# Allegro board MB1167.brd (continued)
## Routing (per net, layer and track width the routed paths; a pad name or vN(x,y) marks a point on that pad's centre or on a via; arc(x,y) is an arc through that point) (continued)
Net_246: length 0.4
  TOP w0.229: 117.36,28.08 v2(117.11,28.33)
NETB2_2: length 17.1
  TOP w0.127: B2.3 66.42,10.3 C100.2 66.42,11.94 66.04,12.32 58.67,12.32 R217.1 R216.1 55.95,10.99 B2.2
NETB3_1: length 45.4
  TOP w0.127: v1(56.9,33.96) 57.34,34.41 U22.20 ; C93.2 R212.2 73.53,13.84 v1(72.9,13.21) 71.25,13.21 68.58,10.54 68.58,8.11 B3.1
  L4_SIG w0.102: v1(72.9,13.21) 72.69,13.41 69.8,13.41 68.48,14.73 66.55,14.73 59.05,22.23 59.05,32.77 57.86,33.96 v1(56.9,33.96)
NETB3_2: length 40.4
  TOP w0.127: R211.2 C92.2 v1(69.34,13.08) 69.34,12.7 67.94,11.3 67.94,7.24 69.86,5.32 B3.2 ; U22.18 v1(57.66,33.41)
  L4_SIG w0.102: v1(57.66,33.41) 57.91,33.41 58.67,32.64 58.67,22.1 66.47,14.3 68.12,14.3 v1(69.34,13.08)
NETB3_3: length 43
  TOP w0.127: U22.19 57.53,33.9 v1(56.9,33.27) ; C91.2 R210.2 v1(67.94,13.08) 67.44,12.57 67.44,6.6 69.72,4.32 72.37,4.32 B3.3
  L4_SIG w0.102: v1(67.94,13.08) 67.13,13.89 66.37,13.89 58.42,21.84 58.42,32.38 57.91,32.89 57.28,32.89 v1(56.9,33.27)
NETB3_4: length 52.8
  TOP w0.127: v1(52.3,35.69) 52.17,35.81 51.18,35.81 50.77,35.41 U22.39 ; B3.4 79.76,11.31 v1(79.76,13.08) 79.76,13.34 R214.2 C95.2
  L4_SIG w0.102: v1(79.76,13.08) 78.49,14.35 70.26,14.35 68.99,15.62 66.55,15.62 59.74,22.43 59.74,33.1 58.19,34.65 53.14,34.65 52.3,35.48 v1(52.3,35.69)
NETB3_6: length 46.5
  TOP w0.127: C94.2 R213.2 76.71,13.59 v1(76.71,13.07) B3.6 ; U22.40 50.99,34.9 v1(51.29,35.2)
  L4_SIG w0.102: v1(76.71,13.07) 75.94,13.84 70,13.84 68.73,15.11 66.67,15.11 59.33,22.46 59.33,33 57.91,34.42 52.07,34.42 v1(51.29,35.2)
NETBT1_1: length 26.2
  TOP w0.254: BT1.1 47.88,78.23 44.07,82.04 44.07,97.79 JP9.3
NETC2_1: length 6.9
  TOP w0.508: C4.1 137.79,167.26 C2.1 R1.2 134.85,168.68 U1.6
NETC5_1: length 10
  TOP w0.508: U2.1 135.14,160.21 ; U2.1 135.14,158 ; U2.1 134.43,159.11 ; U2.1 135.85,159.11 ; C5.1 135.84,161.93 ; C5.1 135,162.89 ; C5.1 135,160.96 ; R15.2 138.91,157.61 ; R15.2 138.3,158.2 ; R15.2 137.69,157.61 ; R6.1 138.91,159.13 ; R6.1 138.3,158.53 ; R6.1 137.69,159.13
NETC6_2: length 49.3
  TOP w0.127: CN1.31 64.01,166.53 v1(64.01,163.96) 64.01,160.2 64.17,160.04 65.55,160.04 C6.2
  BOTTOM w0.127: SB34.1 39.24,145.8 38.73,146.3 38.73,154.56 44.86,160.68 52.7,160.68 55.98,163.96 v1(64.01,163.96)
NETC7_2: length 83
  TOP w0.127: C7.2 72.14,161.8 71.63,162.31 71.63,166.21 CN1.27
  TOP w0.155: v1(69.44,157.84) 69.6,157.99 69.6,159.89 69.98,160.27 C7.2
  BOTTOM w0.127: v1(69.44,157.84) 69.67,157.84 69.82,157.99 80.16,157.99 80.82,158.65 93.24,158.65 93.65,159.05 101.55,159.05 102.86,157.75 102.86,156.5 107.31,152.04 107.31,134.65 109.25,132.72 112.65,132.72 113.92,133.99 115.32,133.99 SB48.1 116.2,133.1
NETC8_2: length 28.2
  TOP w0.127: CN1.33 61.09,166.15 v1(61.09,162.62) C8.2
  BOTTOM w0.127: SB23.1 47.62,153.92 56.32,162.62 v1(61.09,162.62)
NETC9_2: length 33.6
  TOP w0.127: CN1.34 62.48,165 v1(62.48,161.99) C9.2
  BOTTOM w0.127: v1(62.48,161.99) 62.29,161.8 59.31,161.8 49.28,151.76 49.28,149.35 48.39,148.46 45.47,148.46 44.7,147.7 43.05,147.7 42.63,148.12 41.53,148.12 41.32,148.34
NETC10_2: length 78.9
  TOP w0.127: v1(67.94,155.32) 67.94,156.51 68.07,156.64 68.07,159.51 C10.2 68.83,166.47 CN1.29
  BOTTOM w0.127: v1(67.94,155.32) 67.94,155.55 69.06,156.67 69.8,156.67 70.36,157.23 80.72,157.23 81.25,157.76 95.5,157.76 96.22,158.47 100.91,158.47 101.73,157.66 101.73,157.23 106.93,152.02 106.93,134.42 109.22,132.13 SB50.1 109.22,130.56
NETC11_1: length 47.6
  TOP w0.127: v1(74.52,158.5) 74.55,158.5 74.8,158.75 R7.2 C11.1
  BOTTOM w0.127: SB53.2 50.32,132.23 50.32,137.85 55.12,142.65 55.12,147.99 61.37,154.24 64.71,154.24 68.2,157.73 68.66,157.73 69.22,158.29 74.14,158.29 74.35,158.5 v1(74.52,158.5)
NETC12_2: length 46.5
  TOP w0.127: C12.2 R8.1 78.51,159.74 v1(78.51,160.27)
  BOTTOM w0.127: v1(78.51,160.27) 77.72,160.27 77.09,159.64 73.43,159.64 73.18,159.38 68.58,159.38 68.2,159 66.55,159 63.5,155.96 61.09,155.96 53.59,148.46 53.59,143.76 SB44.2
NETC13_2: length 56.4
  TOP w0.127: C13.2 R9.1 81.97,159.59 v1(81.97,160.73)
  BOTTOM w0.127: 40.56,141.4 41.16,140.8 42.89,140.8 43.43,141.35 45.02,141.35 45.4,141.73 48.77,141.73 52.45,145.41 52.45,149.1 60.45,157.1 62.99,157.1 66.07,160.17 67.87,160.17 68.39,160.7 72.97,160.7 73.17,160.5 76.28,160.5 77.07,161.29 81.41,161.29 v1(81.97,160.73)
NETC14_2: length 52.6
  TOP w0.127: v1(85.9,162.92) 85.85,162.86 85.85,162.31 86.23,161.93 86.23,159.38 R10.1 C14.2
  BOTTOM w0.127: v1(85.9,162.92) 85.5,163.32 65.66,163.32 62.99,160.66 59.05,160.66 50.04,151.64 50.04,148.84 48.77,147.57 SB31.2
NETC15_1: length 92.6
  TOP w0.127: v1(88.9,168.91) 89.15,168.66 89.15,159.51 R11.2 R12.1 C15.1
  BOTTOM w0.127: 40.64,139.83 SB40.2 39.12,139.83 37.21,141.73 37.21,156.21 42.55,161.54 42.55,166.75 45.19,169.39 88.42,169.39 v1(88.9,168.91)
NETC16_2: length 10.6
  TOP w0.127: CN1.1 104.27,166.59 C16.2 R13.1 R14.1
NETC17_1: length 1.7
  TOP w0.127: C17.1 64.32,158.88 64.14,159.05
NETC18_2: length 78.4
  TOP w0.127: v1(69.34,156.21) 70.49,157.36 70.49,159 SB1.1 ; C18.2 70.87,158.88
  BOTTOM w0.127: SB56.1 115.32,127.76 112.67,127.76 112.27,127.36 107.87,127.36 107.59,127.64 107.59,132.87 106.22,134.24 106.22,151.51 100.89,156.84 100.41,156.84 99.2,158.05 96.22,158.05 95.66,157.48 81.51,157.48 81,156.97 70.54,156.97 69.77,156.21 v1(69.34,156.21)
NETC20_1: length 6.3
  TOP w0.203: X1.2 75.44,152.65 C20.1 R19.2
NETC21_1: length 5.7
  TOP w0.203: R17.1 C21.1 82.09,151.17 82.09,152.06 82.63,152.6 82.63,153.46 X2.1
NETC22_1: length 5.7
  TOP w0.203: X2.2 83.06,153.28 83.06,152.4 82.51,151.85 82.51,151.02 C22.1 R18.1
NETC24_2: length 2.8
  TOP w0.127: R29.1 C24.2 R30.1
NETC25_1: length 2.4
  TOP w0.127: U5.1 26.89,133.77 C25.1
NETC25_2: length 2.1
  TOP w0.127: C25.2 26.02,133.12 U5.2
NETC27_2: length 2.4
  TOP w0.127: U5.3 26.67,132.47 C27.2
NETC30_1: length 13.9
  TOP w0.254: C30.1 137.54,125.22 X4.1 145.29,125.22 JP6.1
NETC31_2: length 7.2
  TOP w0.254: X4.2 140.72,121.28 139.19,122.81 R73.2 C31.2
NETC32_1: length 12.8
  TOP w0.127: v5(81.21,134.49) U4.E11
  TOP w0.508: C32.1 80.82,127.05 80.7,127.18 79.58,128.29 v1(79.58,128.29)
  BOTTOM w0.127: v5(81.21,134.49) 80.83,134.11 80.16,134.11 80.01,133.96 80.01,132.59 79.88,132.46
  BOTTOM w0.381: v1(79.58,128.29) 79.76,128.47 79.76,130.77 79.78,130.79 79.78,132.36 79.88,132.46
NETC34_1: length 21.4
  TOP w0.508: 4.47,118.11 C35.1 ; C35.1 5.69,118.11 ; C35.1 5.08,117.46 ; CN8.6 5.46,110.88 ; CN8.6 3.46,110.88 ; CN8.6 4.46,110.14 ; CN8.7 4.46,116.17 ; CN8.7 5.46,115.43 ; CN8.7 3.46,115.43 ; C44.1 5.08,108.6 ; C44.1 4.47,107.95 ; C44.1 5.69,107.95 ; 2.44,109.01 CN8.9 1.28,108.1 ; 6.6,117.46 L1.2 ; L1.2 7.21,118.11 ; L1.2 5.99,118.11 ; L1.2 6.6,118.76 ; 2.95,118.11 C34.1 ; C34.1 4.17,118.11 ; C34.1 3.56,117.46 ; 2.95,107.95 C43.1 ; C43.1 4.17,107.95 ; C43.1 3.56,108.6 ; 1.28,118.21 CN8.8 2.44,117.31 ; 5.01,114.46 CN8.5 3.26,114.46
NETC36_1: length 8.8
  TOP w0.508: U7.1 17.09,116.26 C36.1 15.62,116.46 SB13.2 13.84,116.46 12.07,116.46 11.43,115.82 SB12.1
NETC38_1: length 8
  TOP w0.203: X5.1 27.81,113.54 C38.1 R87.2 28.7,109.86 U8.28
NETC39_1: length 7.6
  TOP w0.203: X5.2 29.34,113.54 C39.1 R87.1 29.2,110.61 U8.27
NETC40_1: length 12.4
  TOP w0.102: U9.B5 81.31,102.77 83.11,102.77 83.79,103.45 83.79,105.87 84,106.07 84,107.95
  TOP w0.127: 84,107.95 84,110.41 C40.1 R85.2
NETC41_1: length 5
  TOP w0.127: U8.29 28.2,109.72 27.81,110.11 v1(27.05,110.11) 26.92,110.11 C41.1
  BOTTOM w0.127: C142.1 26.67,110.11 v1(27.05,110.11)
NETC42_1: length 19.4
  TOP w0.254: v1(30.1,111.53) 30.23,111.53 30.86,110.9 C42.1 29.7,109.58 U8.26 ; U8.15 29.7,102.74
  TOP w0.381: v1(32,102.79) 32,101.47 C47.1 31.11,101.35 29.97,102.49 29.95,102.49 29.7,102.74
  BOTTOM w0.381: v1(32,102.79) 32,103 32.38,103.38 32.38,110.03 30.89,111.53 v1(30.1,111.53)
NETC49_2: length 1.9
  TOP w0.508: C49.2 21.15,72.45 U16.4
NETC50_2: length 19.9
  TOP w0.508: U16.1 25.27,70.48 C52.2 C50.2 ; C50.2 27.12,72.45 U16.3 ; C50.2 27.18,73.28 27.69,73.79 28.57,73.79 29.06,74.28 D12.2 D11.2 D10.2 D9.2 D8.2 D7.2
NETC60_1: length 27.3
  TOP w0.508: 21.97,46.46 Z1.2 ; Z1.2 23.17,47.5 ; Z1.2 20.76,47.5 ; Z1.2 21.97,48.54 ; C60.1 21.48,44.96 ; C60.1 20.83,45.57 ; C60.1 20.83,44.35 ; 20.7,42.38 D13.3 ; D13.3 21.37,42.89 ; D13.3 20.7,43.4
  TOP w1.143: 21.08,49.78 20.19,50.67 13.46,50.67 11.43,52.7 9.02,52.7 6.52,50.2 L3.1
NETC60_2: length 27
  TOP w0.508: 19.3,44.35 C60.2 ; C60.2 18.66,44.96 ; C60.2 19.3,45.57 ; CN17.2 9.86,34.62 ; CN17.2 5.23,34.62 ; CN17.2 7.54,33.4 ; CN17.2 7.54,35.84 ; 18.17,46.46 Z1.1 ; Z1.1 16.96,47.5 ; Z1.1 18.17,48.54 ; Z1.1 19.37,47.5 ; 19.43,42.89 19.43,43.4 ; 19.43,42.89 18.76,42.89 ; 19.43,42.89 19.43,42.38 ; CN17.3 4.45,41.94 ; CN17.3 5.66,39.62 ; CN17.3 3.23,39.62 ; CN17.3 4.45,37.31 ; L3.2 10.3,50.2 ; L3.2 7.91,50.2 ; L3.2 9.1,51.4 ; L3.2 9.1,49.01
NETC62_1: length 9
  TOP w0.508: 65.07,35.05 65.91,35.05 ; 65.91,35.05 65.91,36.02 ; 65.91,35.05 65.91,34.09 ; 65.91,35.05 66.75,35.05 ; 66.14,38.86 L5.2 65.53,38.21 ; C62.1 65.28,37.69 ; C62.1 65.28,36.47 ; C62.1 65.93,37.08 ; CN20.45 65.72,33.46
NETC62_2: length 11.3
  TOP w0.508: C62.2 63.75,37.69 ; C62.2 63.11,37.08 ; C62.2 63.75,36.47 ; L4.2 64.11,38.86 ; L4.2 62.89,38.86 ; L4.2 63.5,38.21 ; 62.61,31.24 CN20.49 63.18,32.84 ; 62.28,35.05 C70.2 ; C70.2 63.12,34.09 ; C70.2 63.12,36.02 ; C70.2 63.96,35.05 ; 64.39,33.02 64.45,32.96 CN20.47
NETC63_2: length 5.2
  TOP w0.127: U23.C9 116.97,31.48 116.97,32.13 116.46,32.64 115.7,32.64 C63.2
NETC64_1: length 5.4
  TOP w0.089: U23.D7 117.61,30.34 117.61,31.49 117.6,31.5
  TOP w0.127: 117.6,31.5 117.47,31.62 117.47,32.26 C64.1
NETC64_2: length 60.5
  TOP w0.127: v1(135.2,2.49) 136.51,1.18 CN26.2 140.37,1.18 R223.2 ; R177.1 v1(111.63,28.32) ; v1(114.58,35.18) 114.68,35.28 114.68,35.31 C64.2
  L4_SIG w0.102: v1(111.63,28.32) 111.63,18.41 119.89,10.16 127.64,10.16 130.81,6.99 130.81,4.19 132.51,2.49 v1(135.2,2.49)
  BOTTOM w0.127: v1(111.63,28.32) 111.63,30.17 112.87,31.4 112.87,34.38 113.67,35.18 v1(114.58,35.18)
NETC65_1: length 3.8
  TOP w0.089: U23.D9 117.86,31.5
  TOP w0.127: 117.86,31.5 117.86,32.38 116.71,33.53 C65.1
NETC69_1: length 7.2
  TOP w0.089: 119.61,31.5 119.61,31.01 119.61,31 119.61,30.98 119.46,30.84 119.26,30.84 119.11,30.69 119.11,30.48 118.96,30.33 118.76,30.33 118.61,30.19 118.61,29.84 118.36,29.59 U23.E6
  TOP w0.127: C69.1 121.79,33.91 121.79,33.15 121.16,32.51 120.27,32.51 119.61,31.86 119.61,31.5
NETC71_1: length 6.2
  TOP w0.089: 120.4,30.73 120.25,30.58 U23.H8
  TOP w0.127: C71.1 124.38,32.18 122.99,32.18 121.54,30.73 120.4,30.73
NETC71_2: length 5.2
  TOP w0.089: U23.G8 119.51,30.58 119.76,30.83 120.04,30.83 120.4,31.19
  TOP w0.127: 120.4,31.19 121.36,31.19 122.68,32.51 123.19,32.51 C71.2
NETC72_2: length 47.7
  TOP w0.127: U23.A7 116.34,30.1 115.06,30.1 C72.2 v1(114.05,32)
  L4_SIG w0.102: v1(114.05,32) 113.54,31.5 110.07,31.5 98.77,20.19 85.98,20.19 83.69,17.91 83.69,14.35 JP17.1
NETC73_1: length 4.8
  TOP w0.089: 120.4,30.33 119.96,30.33 119.96,30.33 119.61,30.33 119.36,30.08 U23.G7
  TOP w0.127: C73.1 123.44,31.5 122.28,30.33 120.4,30.33
NETC74_2: length 5.5
  TOP w0.089: 115.82,29.84 116.61,29.84 U23.B6
  TOP w0.127: 115.82,29.84 115.18,29.84 114.55,29.21 R177.2 C74.2
NETC75_1: length 3.9
  TOP w0.089: 120.4,29.95 120.26,30.08 U23.H7
  TOP w0.127: 120.4,29.95 123.29,29.95 C75.1
NETC76_1: length 34.9
  TOP w0.089: 120.4,29.59 120.15,29.84 119.61,29.84 U23.G6
  TOP w0.127: CN26.4 131.99,5.88 v1(132.31,6.2) ; 120.4,29.59 122.18,29.59 v1(122.56,29.21) 122.94,28.83 C76.1
  L4_SIG w0.102: v1(122.56,29.21) 124.08,27.69 125.86,27.69 127.95,25.59 127.95,21.15 132.31,16.79 v1(132.31,6.2)
NETC76_2: length 1.7
  TOP w0.127: C76.2 R178.1
NETC77_1: length 28.6
  TOP w0.089: 120.4,29.21 120.23,29.21 U23.H6
  TOP w0.127: v1(124.33,28.19) C77.1 121.79,29.21 120.4,29.21 ; CN26.6 137.32,14.33 v1(135.74,14.33)
  L4_SIG w0.102: v1(135.74,14.33) 135.28,14.33 128.22,21.39 128.22,25.96 125.98,28.19 v1(124.33,28.19)
NETC77_2: length 1.7
  TOP w0.127: C77.2 R179.1
NETC78_2: length 7.7
  TOP w0.279: U22.9 55.73,27.33 C78.2
  TOP w0.508: C78.2 56.01,26.04 56.26,25.78 C82.1 56.13,24.13 L6.2
NETC79_2: length 5.1
  TOP w0.127: U22.7 54.73,27.55 C79.2 R182.1 52.98,27.29 D16.1
NETC87_1: length 4
  TOP w0.127: U23.F1 119,26.94 119,26.42 120.14,25.27 120.14,24.89 C87.1
NETC88_1: length 2.5
  TOP w0.127: C88.1 R197.1 R196.1
NETC88_2: length 13.1
  TOP w0.254: U23.A2 116.21,27.43 115.32,27.43
  TOP w0.508: 115.32,27.43 114.93,27.04 114.29,27.04 112.78,25.53 112.78,20.07 114.17,18.67 C88.2
NETC97_1: length 5.8
  TOP w0.127: R215.2 C97.1 101.22,9.91 CN28.1
NETC98_1: length 3.1
  TOP w0.127: R220.2 R219.2 106.68,9.53 C98.1
NETC98_2: length 22.2
  TOP w0.229: U23.B3 v2(116.61,28.33)
  TOP w0.508: v1(113.92,28.19) 113.03,28.19 106.68,21.84 C98.2
  L4_SIG w0.381: v2(116.61,28.33) 116.24,28.7 114.43,28.7 v1(113.92,28.19)
NETC100_1: length 1.5
  TOP w0.127: C100.1 R218.2
NETC134_2: length 3.2
  TOP w0.127: v1(33.15,133.22) 33.25,133.12 U5.27
  BOTTOM w0.127: v1(33.15,133.22) 33.78,132.59 C134.2
NETC136_1: length 4.9
  TOP w0.127: v1(31.5,131.83) 33.53,131.83 34.19,131.17 U5.24
  BOTTOM w0.127: v1(31.5,131.83) C136.1
NETC136_2: length 4.8
  TOP w0.127: U5.28 31.91,133.77 v1(31.5,133.35)
  BOTTOM w0.127: v1(31.5,133.35) C136.2
NETC137_2: length 9.2
  TOP w0.254: v1(130.3,116.33) 130.27,116.37 U6.23 ; U6.18 v1(127.77,116.33) ; U6.37 130.77,125.31 v1(130.3,124.84)
  BOTTOM w0.508: v1(127.77,116.33) 127.38,116.72 C141.2 ; C137.2 v1(130.3,124.84) 130.3,124.08 C139.1 ; C140.1 v1(130.3,116.33)
NETC138_1: length 10.4
  TOP w0.127: U4.L11 v5(75.61,134.49)
  BOTTOM w0.127: 76.83,132.41 76.83,133.88 76.61,134.11 75.99,134.11 v5(75.61,134.49)
  BOTTOM w0.381: 76.83,132.41 76.83,132.03 77.11,131.75 77.11,131.57 78.11,130.58 78.11,126.19 C138.1
NETCN1_3: length 78
  L4_SIG w0.102: v1(117.27,121.21) 117.27,123.75 121.67,128.14 125.22,128.14 129.67,132.59 129.67,135.89 v1(130.18,136.4)
  BOTTOM w0.127: CN1.3 102.33,169.29 113.79,169.29 116.2,166.88 116.2,163.7 125.35,154.56 125.35,152.35 130.35,147.35 130.35,136.58 v1(130.18,136.4) ; SB62.2 116.08,122.4 v1(117.27,121.21)
NETCN1_5: length 64.9
  TOP w0.127: CN1.5 96.9,166.4 v1(96.9,162.13)
  BOTTOM w0.127: 47.7,144.45 48.82,144.45 51.1,146.74 51.1,149.78 60.58,159.26 62.99,159.26 66.17,162.43 84.38,162.43 85.01,161.8 86.49,161.8 86.82,162.13 v1(96.9,162.13)
NETCN1_9: length 79.4
  TOP w0.127: v1(94.11,158.22) 94.11,166.59 CN1.9
  BOTTOM w0.127: SB59.1 47.5,125.73 51.08,129.31 51.08,137.62 55.85,142.39 55.85,147.65 61.65,153.45 65.05,153.45 68.55,156.95 69.62,156.95 70.15,157.48 80.52,157.48 81.08,158.04 93.93,158.04 v1(94.11,158.22)
NETCN1_11: length 56
  TOP w0.127: v1(92.96,156.97) 92.84,157.1 92.84,161.16 91.69,162.31 91.69,166.47 CN1.11
  BOTTOM w0.127: v1(92.96,156.97) 93.55,156.39 99.03,156.39 104.75,150.67 104.75,133.55 106.3,132 106.3,126.62 106.68,126.24 110.49,126.24 110.74,125.98 SB58.2
NETCN1_13: length 84.2
  BOTTOM w0.127: CN1.13 86.58,169.04 45.72,169.04 43.05,166.37 43.05,161.54 37.59,156.08 37.59,142.37 39.41,140.55 43.73,140.55 44.2,140.08 46.61,140.08 47.37,140.84 SB39.1
NETCN1_14: length 5
  TOP w0.127: CN1.14 88.39,164.69 R11.1
NETCN1_15: length 8.5
  TOP w0.127: R10.2 85.09,160.78 85.09,162.69 84.2,163.58 84.2,166.4 CN1.15
NETCN1_17: length 8.1
  TOP w0.127: R9.2 82.8,162.94 81.92,163.83 81.92,166.65 CN1.17
NETCN1_19: length 8.1
  TOP w0.127: CN1.19 78.99,166.27 78.99,163.83 79.3,163.53 79.3,160.48 R8.2
NETCN1_21: length 62.4
  TOP w0.127: v1(78.37,159.25) 78.37,159.31 78.03,159.65 78.03,162.76 76.58,164.21 76.58,166.4 CN1.21
  BOTTOM w0.127: SB46.2 108.58,136.53 108.58,137.82 108.08,138.33 108.08,154.05 106.43,155.7 106.43,157.48 103.92,159.98 93.21,159.98 92.68,159.46 81.2,159.46 80.59,160.07 79.55,160.07 78.73,159.25 v1(78.37,159.25)
NETCN1_23: length 62.2
  TOP w0.127: v1(77.6,159.26) 77.6,160.96 75.95,162.61 75.64,162.61 74.04,164.21 74.04,166.4 CN1.23
  BOTTOM w0.127: v1(77.6,159.26) 78.11,159.77 78.73,159.77 79.32,160.35 80.75,160.35 81.38,159.72 92.46,159.72 93.05,160.31 104.33,160.31 106.93,157.71 106.93,156.21 108.46,154.69 108.46,139.19 109.22,138.43
NETCN1_26: length 5.9
  TOP w0.127: CN1.26 72.74,163.86 75.31,161.29 R7.1
NETCN2_1: length 3.1
  TOP w0.127: R3.2 CN2.1
NETCN2_3: length 3.1
  TOP w0.127: CN2.3 36.16,163.96 R5.2
NETCN2_4: length 9
  TOP w0.127: R16.1 24.77,157.1 24.77,162.69 25.91,163.83 CN2.4
NETCN3_1: length 4.8
  TOP w0.127: CN3.1 R29.2 R28.1
NETCN4_15: length 179.9
  TOP w0.127: v1(53.21,36.83) 53.21,36.96 53.23,36.98 U22.33 ; v1(150.62,149.69) CN4.15
  L4_SIG w0.102: v1(53.21,36.83) 54.1,37.72 75.18,37.72 116.33,78.87 116.33,87.05 131.04,101.75 131.04,106.4 134.37,109.73 136.75,109.73 141.02,114 142.82,114 146.18,117.35 153.47,117.35 155.19,119.08 155.19,133.86 153.8,135.25 153.8,146.52 v1(150.62,149.69)
  BOTTOM w0.127: R229.2 150.62,149.86 v1(150.62,149.69)
NETCN4_17: length 176.2
  TOP w0.127: v1(53.59,39.24) 53.73,39.1 U22.32 ; v1(150.55,148.39) 150.12,148.39 149.81,148.69 CN4.17
  L4_SIG w0.102: v1(53.59,39.24) 54.74,38.1 75.06,38.1 115.95,78.99 115.95,87.07 130.68,101.8 130.68,106.55 134.11,109.98 136.53,109.98 140.91,114.36 142.68,114.36 146.05,117.73 150.5,117.73 153.03,120.27 153.03,128.4 154.81,130.18 154.81,133.6 153.42,135 153.42,146.05 151.08,148.39 v1(150.55,148.39)
  BOTTOM w0.127: R231.1 150.55,148.41 v1(150.55,148.39)
NETCN4_18: length 32.2
  TOP w0.127: CN4.18 153.44,148.69 156.08,146.05 156.08,121.41 TP7.1
NETCN4_19: length 173.6
  TOP w0.127: v1(54.36,39.24) 54.23,39.12 U22.31 ; CN4.19 149.82,147.69 150.47,147.04 v1(150.55,147.04)
  L4_SIG w0.102: v1(54.36,39.24) 55.24,38.35 74.95,38.35 115.7,79.1 115.7,87.17 130.43,101.9 130.43,106.81 133.86,110.24 136.42,110.24 140.85,114.67 142.61,114.67 146.43,118.49 150.37,118.49 152.65,120.78 152.65,128.78 154.43,130.56 154.43,133.35 153.03,134.75 153.03,145.54 151.54,147.04 v1(150.55,147.04)
  BOTTOM w0.127: v1(150.55,147.04) 149.73,146.23 R235.1
NETCN4_32: length 155
  TOP w0.127: JP23.1 113.79,51.69 R301.1 113.79,55.5 113.28,56.01 93.73,56.01 93.09,56.64 v1(89.03,56.64) ; CN4.32 151.57,141.69 151.03,141.15 v1(151.03,140.51)
  L4_SIG w0.102: v1(89.03,56.64) 90.04,56.64 111.96,78.56 111.96,88.06 116.36,92.46 117.89,92.46 125.22,99.79 125.22,100.68 126.21,101.68 127.51,101.68 128.27,102.44 128.27,104.72 126.72,106.27 126.52,106.27 125.5,107.29 125.5,110.79 128.09,113.39 132.33,113.39 135.53,116.59 138.66,116.59 139.27,117.2 142.32,117.2 148.03,122.91 149.66,122.91 150.01,123.27 150.01,127.3 153.44,130.73 153.44,133.71 152.25,134.9 152.25,139.75 151.49,140.51 v1(151.03,140.51)
NETCN4_33: length 63.1
  TOP w0.127: v1(110.11,160.53) 109.73,160.15 SB5.1 ; v1(147.98,140.87) 148.16,140.69 CN4.33
  L4_SIG w0.102: v1(147.98,140.87) 149.48,142.37 150.88,142.37 151.12,142.61 151.12,143.01 150.85,143.28 150.85,143.99 151.38,144.53 151.38,145.16 150.88,145.67 150.11,145.67 149.31,146.47 149.31,156.76 147.37,158.7 126.42,158.7 125.65,159.46 111.18,159.46 v1(110.11,160.53)
NETCN4_34: length 21.8
  TOP w0.127: CN4.34 154.33,140.69 155.57,139.45 155.57,123.44 TP8.1
NETCN4_35: length 18.1
  TOP w0.127: TP11.1 154.05,134.75 152.4,136.4 148.97,136.4 148.21,137.16 148.21,139.19 148.71,139.69 CN4.35
NETCN4_36: length 17.7
  TOP w0.127: TP10.1 154.18,124.33 155.07,125.22 155.07,138.43 153.8,139.69 CN4.36
NETCN5_3: length 40.6
  TOP w0.127: v1(43.23,154.23) 43,154.23 42.55,154.69 CN5.3
  L4_SIG w0.102: v1(78.11,149.88) 77.87,150.11 73.03,150.11 70.54,152.6 55.8,152.6 53.26,155.14 45.77,155.14 44.86,154.23 v1(43.23,154.23)
  BOTTOM w0.127: 76.93,149.88 v1(78.11,149.88)
NETCN5_5: length 3.1
  TOP w0.127: v1(39.5,153.42) CN5.5
  BOTTOM w0.127: R224.2 v1(39.5,153.42)
NETCN5_6: length 29.3
  TOP w0.127: CN5.6 47.85,153.42 v1(49,154.56)
  L4_SIG w0.102: v1(72.39,150.11) 71.88,150.11 69.77,152.22 55.55,152.22 53.21,154.56 v1(49,154.56)
  BOTTOM w0.127: 73.76,149.88 72.62,149.88 v1(72.39,150.11)
NETCN6_3: length 37.4
  TOP w0.127: v1(111.81,154.05) 111.18,154.69 CN6.3
  L4_SIG w0.102: v1(79.22,150.22) 79.98,150.22 80.34,150.57 87.68,150.57 91.31,154.2 111.66,154.2 v1(111.81,154.05)
  BOTTOM w0.127: SB26.2 80.24,150.22 v1(79.22,150.22)
NETCN6_4: length 35
  TOP w0.127: CN6.4 114.17,154.69 113.61,154.13 v1(113.49,154.13)
  L4_SIG w0.102: v1(84.02,151.61) 84.71,150.93 87.5,150.93 91.16,154.58 111.94,154.58 112.39,154.13 v1(113.49,154.13)
  BOTTOM w0.127: SB25.2 83.95,151.54 v1(84.02,151.61)
NETCN7_2: length 32.2
  TOP w0.127: CN7.2 11.91,139.29 16.64,144.02 22.73,144.02 26.16,140.59 26.16,138.3 29.84,134.62 29.84,131.44 28.92,130.52 U5.6
NETCN7_3: length 25.1
  TOP w0.127: U5.10 25.93,127.91 24.26,126.24 17.65,126.24 14.35,129.54 14.35,133.86 11.68,136.53 CN7.3
NETCN7_6: length 34.9
  TOP w0.127: U5.5 28.68,131.17 29.21,131.7 29.21,134.49 25.65,138.05 25.65,140.34 22.35,143.64 17.27,143.64 11.68,138.05 9.53,138.05 7.49,140.08 CN7.6
NETCN7_8: length 30.4
  TOP w0.127: U5.7 27,129.87 26.8,129.67 26.8,129.29 24.26,126.75 17.91,126.75 15.11,129.54 15.11,133.86 11.3,137.67 9.4,137.67 7.49,135.76 CN7.8
NETCN8_2: length 27.8
  TOP w0.155: v1(8.44,113.97) 8.2,113.97 7.8,114.37 D4.A1 7.8,114.49 7.46,114.49 5.61,112.64 5.12,112.64 4.99,112.51 CN8.2 ; v1(23.34,104.09) 23.48,104.23 25.26,104.23 25.39,104.35 25.59,104.35 25.65,104.29 U8.8
  L4_SIG w0.13: v1(23.34,104.09) 23.2,104.23 22.74,104.23 21.38,105.59 20.62,105.59 11.6,114.6 9.47,114.6 8.84,113.97 v1(8.44,113.97)
NETCN8_3: length 27.7
  TOP w0.155: U8.7 25.71,104.8 25.65,104.74 25.23,104.74 25.11,104.61 23.48,104.61 v1(23.34,104.75) ; CN8.3 4.99,113.16 5.12,113.02 5.45,113.02 7.3,114.87 7.79,114.87 D4.A2 7.8,115.04 8.2,115.44 v1(8.38,115.44)
  L4_SIG w0.13: v1(8.38,115.44) 8.97,115.44 9.42,114.99 11.76,114.99 20.78,105.97 21.54,105.97 22.9,104.61 23.2,104.61 v1(23.34,104.75)
NETCN8_4: length 29
  TOP w0.127: v1(8.66,117.09) 8.08,117.09 7.8,116.81 D3.A2 7.06,116.53 6.48,115.95 6.48,114.94 5.35,113.81 CN8.4 ; v1(23.37,105.8) U8.5
  L4_SIG w0.102: v1(23.37,105.8) 22.94,105.8 14.61,114.13 14.61,114.71 12.22,117.09 v1(8.66,117.09)
NETCN9_1: length 35.8
  TOP w0.13: U6.17 127.27,118.34 127.21,118.4 127.21,118.69 126.85,119.04 125.14,119.04 123.95,117.86 123.95,114.35 132.72,105.59 132.72,103.98 134.59,102.11 136.78,102.11 R120.2 138.05,102.11 142.39,102.11 143.06,102.79 143.3,102.79 CN9.1
NETCN9_2: length 35.7
  TOP w0.13: U6.16 126.77,118.34 126.83,118.4 126.83,118.53 126.7,118.66 125.29,118.66 124.33,117.7 124.33,117.44 124.54,117.24 124.54,116.98 124.33,116.78 124.33,116.52 124.54,116.31 124.54,116.05 124.33,115.85 124.33,115.59 124.54,115.39 124.54,115.13 124.33,114.93 124.33,114.51 133.1,105.75 133.1,104.14 134.75,102.49 136.78,102.49 R114.2 138.05,102.49 142.23,102.49 142.9,103.16 142.9,104.01 142.77,104.14 141.73,104.14 141.6,104.01 141.6,103.63
NETCN9_3: length 28
  TOP w0.13: U6.14 125.77,116.55 125.71,116.49 125.71,114.58 130.18,110.11 136.91,110.11 R89.2 138.18,110.11 142.62,110.11 143.13,109.6 143.13,105.92 CN9.3
NETCN9_6: length 28.1
  TOP w0.13: U6.13 125.27,116.55 125.33,116.49 125.33,114.42 130.02,109.73 136.91,109.73 R97.2 138.18,109.73 142.46,109.73 142.75,109.44 142.75,107.42 142.62,107.29 141.48,107.29 141.35,107.42 141.35,108.58 141.48,108.71 141.6,108.71
NETCN9_9: length 3.7
  TOP w0.127: CN9.9 155.39,97.74 R131.1
NETCN9_10: length 39.8
  TOP w0.127: U6.28 132.97,120.54 134.51,119 134.87,119 R76.1 135.89,117.98 137.79,117.98 139.01,116.76 148.79,116.76 150.01,117.98 153.8,117.98 155.19,116.59 v1(155.32,116.59)
  BOTTOM w0.127: CN9.10 153.87,111.2 155.07,112.39 155.07,116.33 v1(155.32,116.59)
NETCN9_11: length 31.9
  TOP w0.127: U6.26 132.98,119.54 133.86,118.67 133.86,117.22 R79.1 135.86,116.43 148.97,116.43 150.01,117.47 153.54,117.47 155.39,115.62 CN9.11
NETCN9_12: length 3.7
  TOP w0.127: R78.1 153.87,116 CN9.12
NETCN11_6: length 47.8
  TOP w0.102: 82.98,107.95 82.98,104.44 U9.A4
  TOP w0.127: 82.98,107.95 82.98,108.46 v4(83.13,108.61) 82.75,108.99 82.75,110.57 R92.1 ; v3(103.5,114.68) 103.68,114.86 CN11.6
  L4_SIG w0.102: v3(103.5,114.68) 103,114.17 101.88,114.17 96.89,109.18 84.42,109.18 83.85,108.61 v4(83.13,108.61)
  BOTTOM w0.127: JP5.1 96.39,118.75 100.99,114.15 102.97,114.15 v3(103.5,114.68)
NETCN12_2: length 58.2
  TOP w0.127: R86.1 123.83,111.12 v1(123.19,110.49) 123.06,110.62 CN12.2 ; v1(146.69,79.76) 146.56,79.76 R141.1 145.8,78.25 145.94,78.11 U15.1 149.24,77.1 CN15.7
  BOTTOM w0.127: v1(123.19,110.49) 123.83,110.49 127.41,106.91 131.35,106.91 133.63,104.63 133.63,101.57 135.64,99.57 139.62,99.57 148.21,90.98 148.21,81.15 146.81,79.76 v1(146.69,79.76)
NETCN12_4: length 59.4
  TOP w0.127: CN12.4 v1(123.06,109.35) 123.83,109.35 R93.1 ; CN15.9 149.61,76.2 145.03,76.2 144.64,76.6 U15.3 144.64,78.11 144.4,78.34 R140.2 v1(145.16,79.76)
  BOTTOM w0.127: v1(123.06,109.35) 126.09,106.32 131.58,106.32 133.12,104.78 133.12,101.45 135.38,99.19 139.37,99.19 147.75,90.8 147.75,82.47 145.16,79.88 v1(145.16,79.76)
NETCN12_6: length 72.4
  TOP w0.127: U15.4 144.64,74.56 R143.1 v1(146.69,73.41) 147.83,73.41 148.46,74.04 150.62,74.04 151.26,73.41 151.26,71.5 CN15.13 ; R111.2 123.83,105.41 v1(123.19,105.41) ; R99.1 123.83,108.08 v1(123.19,108.08) CN12.6
  L4_SIG w0.102: v1(123.19,108.08) 122.68,107.57 122.68,105.92 v1(123.19,105.41)
  BOTTOM w0.127: v1(123.19,108.08) 125.58,105.69 131.67,105.69 132.61,104.75 132.61,101.32 135.28,98.65 139.19,98.65 147.32,90.53 147.32,85.47 144.65,82.8 144.65,76.33 146.69,74.3 v1(146.69,73.41)
NETCN12_8: length 47.6
  TOP w0.127: CN12.8 v1(123.19,106.81) 123.83,106.81 R101.1 ; CN15.5 147.83,83.06 145.02,83.06 144.64,83.44 U12.5 144.64,85.49 R136.1 v1(145.16,86.49)
  BOTTOM w0.127: v1(123.19,106.81) 126.11,103.89 129.67,103.89 131.32,102.23 131.32,100.97 134.49,97.79 138.81,97.79 145.16,91.44 v1(145.16,86.49)
NETCN12_10: length 63.1
  TOP w0.127: CN12.10 122.17,105.54 122.68,106.05 v1(123.19,106.05) R104.1 ; CN15.15 151.76,69.47 151.76,73.66 150.88,74.55 148.21,74.55 147.7,74.04 146.18,74.04 v1(145.92,74.3) 145.92,75.29 U15.5
  BOTTOM w0.127: v1(145.92,74.3) 144.27,75.95 144.27,84.84 142.37,86.74 142.37,93.6 138.56,97.41 133.73,97.41 130.75,100.39 130.75,101.66 129.03,103.38 125.86,103.38 v1(123.19,106.05)
NETCN12_12: length 98.8
  TOP w0.127: U12.1 v1(143.63,82.16) ; CN12.12 123.01,104.27 v1(123.27,104.52) ; SB7.1 91.82,140.84 92.65,140.02 101.92,140.02 v1(103.25,138.68)
  L4_SIG w0.102: v1(107.98,114.48) 115.39,107.06 120.27,107.06 122.81,104.52 v1(123.27,104.52)
  BOTTOM w0.127: v1(143.63,82.16) 142.89,82.16 139.19,85.85 133.86,85.85 131.57,88.14 131.57,97.16 130.43,98.3 126.62,98.3 125.76,99.16 125.76,102.64 123.88,104.52 v1(123.27,104.52) ; v1(107.98,114.48) 107.98,115.16 106.06,117.08 106.06,118.47 106.05,118.48 106.05,124.33 105.03,125.35 105.03,131.04 103.25,132.82 v1(103.25,138.68)
NETCN12_14: length 64.6
  TOP w0.127: SB8.1 101.98,140.84 103.89,138.94 v1(103.89,138.68) ; CN12.14 123.04,103 v1(123.06,103.02) 123.16,103.12 R111.1 ; v1(123.06,100.58) 123.59,100.06 U10.5
  L4_SIG w0.102: v1(123.06,103.02) 122.78,103.02 119.63,106.17 115.37,106.17 v1(107.98,113.56)
  BOTTOM w0.127: v1(103.89,138.68) 103.89,132.99 105.49,131.39 105.49,125.65 106.55,124.59 106.55,117.47 108.71,115.32 108.71,114.3 v1(107.98,113.56) ; v1(123.06,103.02) 123.7,102.39 123.7,101.22 v1(123.06,100.58)
NETCN12_16: length 67.4
  TOP w0.127: v3(98.98,144.65) SB6.1 ; CN12.16 122.81,101.73 v1(123.06,101.47) 123.18,101.36 U10.4 124.63,101.36 125.25,101.98 125.86,101.98 126.49,102.62 126.49,102.92 126.7,103.12 R113.1
  L4_SIG w0.102: v1(104.32,118.85) 104.32,118.69 106.83,116.18 106.83,113.77 115.7,104.9 119.63,104.9 v1(123.06,101.47)
  BOTTOM w0.127: v1(104.32,118.85) 104.32,119.08 103.5,119.89 103.5,130.58 101.47,132.61 101.47,142.16 v3(98.98,144.65)
NETCN12_18: length 75.9
  TOP w0.127: v1(89.66,149.86) SB3.1 ; CN12.18 122.3,100.46 v1(122.94,99.82) 123.32,99.44 124.84,99.44 125.09,99.69 125.09,101.23 125.22,101.36 U10.3
  L4_SIG w0.102: v1(103.63,118.85) 103.63,118.57 105.97,116.23 105.97,113.49 115.7,103.76 119.51,103.76 122.43,100.84 122.43,100.33 v1(122.94,99.82)
  BOTTOM w0.127: v1(103.63,118.85) 103,119.48 103,130.18 100.58,132.59 100.58,142.11 96.01,146.69 94.23,146.69 91.57,149.35 90.17,149.35 v1(89.66,149.86)
NETCN12_20: length 7.7
  TOP w0.127: 127.89,100.08 127.87,100.06 U10.1 125.99,99.45 125.48,98.93 122.44,98.93 122.18,99.19 CN12.20
NETCN13_2: length 4.7
  TOP w0.155: CN13.2 4.69,99.05 4.83,99.18 6.63,99.18 v1(6.77,99.04) 6.91,99.18 7.44,99.18 D5.D1
  BOTTOM w0.155: v1(6.77,99.04) 7.37,98.45 R284.1
NETCN13_3: length 4.7
  TOP w0.155: D5.C1 7.44,99.56 6.91,99.56 v1(6.77,99.7) 6.63,99.56 4.83,99.56 4.69,99.69 CN13.3
  BOTTOM w0.155: R283.1 7.37,100.29 v1(6.77,99.7)
NETCN13_4: length 7
  TOP w0.127: D5.A3 8.5,101.48 R117.1 6.35,101.6 6.35,100.97 5.73,100.34 CN13.4
NETCN14_2: length 4.7
  TOP w0.155: CN14.2 4.69,84.69 4.83,84.83 6.63,84.83 v1(6.77,84.69) 6.91,84.83 7.44,84.83 D6.D1
  BOTTOM w0.155: R288.1 7.37,84.09 v1(6.77,84.69)
NETCN14_3: length 4.7
  TOP w0.155: CN14.3 4.69,85.34 4.83,85.21 6.63,85.21 v1(6.77,85.35) 6.91,85.21 7.44,85.21 D6.C1
  BOTTOM w0.155: v1(6.77,85.35) 7.37,85.94 R286.1
NETCN14_4: length 76.8
  TOP w0.127: CN14.4 5.09,85.99 6.35,87.25 v1(7.87,87.25) 8,87.25 8.5,86.75 D6.A3 ; v1(39.37,130.56) 38.99,130.56 38.1,129.67 38.1,126.36 36.58,124.84 34.04,124.84 v1(33.66,125.22)
  BOTTOM w0.127: v1(7.87,87.25) 23.88,87.25 35.81,99.19 35.81,118.62 34.67,119.76 34.67,124.08 33.66,125.09 v1(33.66,125.22) ; 40.64,130.56 v1(39.37,130.56)
NETCN15_3: length 40.7
  TOP w0.127: v1(146.56,86.49) R137.1 145.94,85.58 U12.4 145.94,83.69 146.19,83.44 149.99,83.44 CN15.3 ; R112.1 v1(126.95,104.65) R113.2
  BOTTOM w0.127: v1(146.56,86.49) 146.69,86.61 146.69,90.55 139.06,98.17 134.87,98.17 132.08,100.97 132.08,103 130.43,104.65 v1(126.95,104.65)
NETCN15_11: length 6.4
  TOP w0.508: CN15.11 149.1,73.03 148.08,72.01 R144.1 R145.2
NETCN15_17: length 4.2
  TOP w0.127: CN15.17 150.11,65.53 R148.2
NETCN15_19: length 4.3
  TOP w0.127: CN15.19 149.86,62.48 R149.2
NETCN16_1: length 96.7
  TOP w0.127: v1(109.37,80.44) 109.35,80.42 109.35,71.55 136.45,44.45 138.18,44.45 R162.2 140.08,43.69 140.56,44.17 CN16.1
  BOTTOM w0.127: R281.1 108.58,120.9 108.08,120.4 108.08,118.36 110.44,116 110.44,110.11 109.27,108.94 109.27,91.69 110.31,90.65 110.31,81.43 109.37,80.49 v1(109.37,80.44)
NETCN16_2: length 96.5
  TOP w0.127: CN16.2 140.39,45.27 140.34,45.21 R161.2 138.18,45.97 135.64,45.97 109.83,71.78 109.83,80.92 v1(109.35,81.41)
  BOTTOM w0.127: R275.1 107.7,120.9 107.7,118.24 110.03,115.9 110.03,110.34 108.92,109.22 108.92,91.47 109.88,90.5 109.88,81.94 v1(109.35,81.41)
NETCN16_3: length 91.5
  TOP w0.127: v1(110.39,80.44) 110.39,71.98 134.87,47.5 138.18,47.5 R160.2 139.3,46.37 CN16.3
  BOTTOM w0.127: SB63.1 109.22,117.98 110.87,116.33 110.87,109.8 109.63,108.56 109.63,91.9 110.79,90.73 110.79,80.82 110.41,80.44 v1(110.39,80.44)
NETCN16_7: length 96.6
  TOP w0.127: CN16.7 138.97,50.77 R158.2 138.18,51.56 131.72,51.56 110.9,72.39 110.9,80.77 v1(109.32,82.35)
  BOTTOM w0.127: SB61.2 110.74,123.57 110.36,123.19 108.25,123.19 107.19,122.12 107.19,117.98 109.6,115.57 109.6,110.57 108.51,109.47 108.51,91.26 109.4,90.37 109.4,82.42 v1(109.32,82.35)
NETCN16_8: length 99
  TOP w0.127: v1(112.52,80.9) 111.26,79.63 111.26,72.95 131.11,53.09 138.18,53.09 R157.2 139.39,51.87 CN16.8
  BOTTOM w0.127: R260.1 116.46,128.27 116.71,128.27 118.11,126.87 118.11,122.12 118.39,121.84 118.39,119.79 113.16,114.55 113.16,92.71 112.52,92.08 v1(112.52,80.9)
NETCN16_10: length 5.2
  TOP w0.127: R154.2 150.01,55.88 CN16.10
NETCN17_1: length 10.7
  TOP w0.508: D13.1 20.07,39.91 ; D13.1 21.37,39.4 ; D13.1 20.07,38.89 ; D13.1 18.76,39.4 ; CN17.1 11.86,39.62 ; CN17.1 10.64,37.31 ; CN17.1 9.43,39.62 ; CN17.1 10.64,41.94
NETCN19_4: length 2.3
  TOP w0.127: R165.2 CN19.4
NETCN20_22: length 2.8
  TOP w0.127: CN20.22 80.96,24.45 R192.1
NETCN20_39: length 20.1
  TOP w0.127: U22.27 56.23,37.37 v1(56.74,36.86) ; v1(70.23,35.64) 70.18,35.64 69.53,34.99 CN20.39
  L4_SIG w0.102: v1(70.23,35.64) 69.93,35.94 58.37,35.94 57.45,36.86 v1(56.74,36.86)
NETCN20_43: length 116.6
  TOP w0.127: CN20.43 66.99,33.21 73.96,40.18 v1(75.34,40.18)
  BOTTOM w0.127: SB60.1 116.99,123.04 116.99,122.28 117.75,121.51 117.75,120.45 111.86,114.55 111.86,109.52 110.36,108.03 110.36,92.48 112.01,90.83 112.01,80.64 87.88,56.52 87.88,55.3 75.34,42.75 v1(75.34,40.18)
NETCN21_2: length 19
  TOP w0.155: CN21.2 11.49,23.89 11.49,23.73 11.73,23.5 13.97,23.5 14.35,23.88 14.35,28.19 12.07,30.48 12.07,34.29 12.76,34.99 14.16,34.99 14.18,35.01 14.19,35.01 14.73,35.55 R166.1
NETCN21_3: length 21.2
  TOP w0.155: CN21.3 11.11,23.89 11.11,23.58 11.57,23.11 14.13,23.11 14.73,23.72 14.73,28.35 12.45,30.64 12.45,34.13 12.92,34.61 14.16,34.61 14.18,34.59 14.19,34.59 14.73,34.05 R169.1 R171.1
NETCN22_2: length 98
  TOP w0.127: U20.6 135.89,37.47 136.14,37.21 v1(136.14,36.96) 136.14,35.94 134.87,34.67 134.87,30.99 135.84,30.02 138.63,30.02 142.24,26.42 142.24,20.83 140.84,19.43 140.84,17.93 D14.1 145.12,16.7 CN22.2
  BOTTOM w0.127: v1(136.14,36.96) 137.97,38.79 137.97,59.92 127.56,70.33 127.56,95.05 JP12.2
NETCN22_5: length 10
  TOP w0.127: R174.2 145.8,24.64 CN22.5
NETCN22_7: length 35.3
  TOP w0.127: CN22.7 143.27,17.4 D14.2 142.07,19.64 142.88,20.45 142.88,26.67 138.94,30.61 136.14,30.61 135.51,31.24 135.51,34.42 137.41,36.32 R164.1 136.78,38.73 U20.7
NETCN22_9: length 14.8
  TOP w0.127: R170.2 144.04,27.91 145.21,27.91 148.59,24.54 CN22.9
NETCN24_5: length 5.3
  TOP w0.127: CN24.5 123.72,18.81 122.3,17.4 121.54,17.4 R198.1
NETCN25_2: length 8.1
  TOP w0.127: R222.1 117.47,2.54 116.12,1.18 CN25.2
NETCN25_3: length 4.2
  TOP w0.127: CN25.3 115.95,4.53 R221.1
NETCN25_4: length 2.5
  TOP w0.127: R220.1 107.57,5.94 CN25.4
NETCN25_6: length 3.1
  TOP w0.127: CN25.6 115.51,15.47 115.82,15.79 R196.2
NETD1_1: length 106
  TOP w0.127: U5.20 30.95,128.56 v1(30.35,129.16) ; D1.1 v1(97.03,155.52)
  L4_SIG w0.102: v1(97.03,155.52) 95.68,155.52 92.46,158.75 80.9,158.75 80.52,158.37 75.69,158.37 74.55,159.51 35.94,159.51 32.26,155.83 32.26,146.3 27.69,141.73 27.69,131.83 v1(30.35,129.16)
NETD1_2: length 3
  TOP w0.127: JP1.1 98.44,150.13 D1.2
NETD2_2: length 2.4
  TOP w0.127: D2.2 32.51,139.02 JP3.1
NETD5_C3: length 135.5
  TOP w0.155: D5.C3 8.56,99.56 9.09,99.56 v1(9.23,99.7)
  L4_SIG w0.13: v1(113.26,130.02) 112.99,130.29 112.99,130.46 113.14,130.61 114.22,130.61 114.81,130.02 114.81,123.25 113.28,121.72 110.31,121.72 109.07,120.47 99.24,120.47 96.9,118.14 59.21,118.14 57.51,119.84 50.47,119.84 47.88,117.25 47.88,115.14 38.05,105.31 38.05,103.17 33.27,98.4 25.78,98.4 24.18,100 10.26,100 9.82,99.56 9.37,99.56 v1(9.23,99.7)
  BOTTOM w0.127: v1(9.23,99.7) 8.89,100.04 R283.2 ; SB52.1 115.75,129.72 115.49,129.72 115.06,129.29 114.02,129.29 113.28,130.02 v1(113.26,130.02)
NETD15_2: length 1.9
  TOP w0.127: D15.2 41.29,13.97 R209.1
NETJP3_2: length 13.6
  TOP w0.127: U5.16 v1(33.66,125.96)
  BOTTOM w0.127: v1(33.66,125.96) 33.66,126.75 29.97,130.43 JP3.2
NETJP5_3: length 129.9
  TOP w0.127: JP5.3 103.38,124.46 v1(104.27,123.57) ; v1(86.36,55.37) 88.16,53.57 90.2,53.57 95.5,48.26 95.5,23.11 91.31,18.92 87.76,18.92 JP18.3
  BOTTOM w0.127: v1(86.36,55.37) 86.36,56.64 106.81,77.09 106.81,115.32 104.78,117.35 104.78,123.06 v1(104.27,123.57)
NETJP6_2: length 20
  TOP w0.127: v1(134.09,123.7) 133.93,123.54 U6.34
  L4_SIG w0.102: JP6.2 146.18,124.21 142.24,128.14 140.16,128.14 138.35,126.34 136.73,126.34 v1(134.09,123.7)
NETJP6_3: length 53.9
  L4_SIG w0.102: v1(117.25,125.48) 117.25,126.57 134.11,143.43 139.24,143.43 143.59,139.09 143.59,128.57 145.41,126.75 JP6.3
  BOTTOM w0.127: SB57.1 v1(117.25,125.48)
NETJP7_1: length 14.3
  TOP w0.127: U5.17 31.11,126.61 28.64,124.14 23.43,124.14 JP7.1
NETJP7_2: length 138.6
  TOP w0.127: v1(36.83,121.79) 20.83,121.79 19.68,122.94
  BOTTOM w0.127: v1(36.83,121.79) 37.08,121.54 37.08,113.41 42.65,107.85 42.65,88.7 52.81,78.54 52.81,69.11 58.22,63.7 58.22,44.63 54.31,40.72 52.27,40.72 49.53,37.97 49.53,30.25 55.75,24.03 55.75,21.08 57.66,19.18 JP14.1
NETJP7_3: length 161.2
  TOP w0.127: v1(136.53,171.32) 136.75,171.1 U1.4
  BOTTOM w0.127: 17.14,122.94 14.1,125.98 14.1,144.53 17.14,147.57 21.59,147.57 31.11,157.1 32.38,157.1 35.94,160.66 35.94,166.24 41.15,171.45 136.4,171.45 v1(136.53,171.32)
NETJP8_2: length 77
  TOP w0.127: JP8.2 111.76,101.35 115.57,97.54 117.02,97.54 v1(123.37,91.19) ; v1(127.89,36.32) 128.02,36.2 U20.4
  BOTTOM w0.127: v1(123.37,91.19) 123.32,91.19 122.17,90.04 122.17,68.1 127.36,62.92 127.36,36.86 v1(127.89,36.32)
NETJP9_2: length 111.5
  TOP w0.254: 41.15,103.25 39.5,104.9 39.5,115.95 v1(35.69,119.76) ; U4.C1 82.93,143.41 v1(82.93,147.07)
  L4_SIG w0.254: v1(36.32,153.67) 41.27,158.62 53.34,158.62 58.8,153.16 v3(68.45,153.16)
  BOTTOM w0.254: v1(36.32,153.67) 36.32,143.13 35.86,142.67 35.86,137.44 35.18,136.75 35.18,120.27 v1(35.69,119.76) ; v3(68.45,153.16) 68.45,152.65 73,148.11 73,148.09 73.16,147.93 73.18,147.93 74.04,147.07 v1(82.93,147.07)
NETJP10_2: length 11
  TOP w0.102: U9.B4 81.43,103.89 81.99,103.89 82.59,104.48 v5(82.59,104.65)
  TOP w0.127: JP10.2 87.76,101.22 R116.1 86.79,102.74 86.31,103.23 v1(86.31,103.68)
  L4_SIG w0.102: v1(86.31,103.68) 83.55,103.68 v5(82.59,104.65)
NETJP11_2: length 72.9
  TOP w0.127: JP11.2 113.51,96.77 121.06,89.23 122.94,89.23 v1(123.32,89.61) ; U20.8 137.29,40.01 R163.1 v1(137.41,41.02)
  BOTTOM w0.127: v1(123.32,89.61) 123.32,69.34 134.65,58.01 134.65,43.79 v1(137.41,41.02)
NETJP11_3: length 76.7
  TOP w0.127: v1(122.68,89.71) 121.36,89.71 JP11.3 ; R168.1 v1(136.55,34.54)
  BOTTOM w0.127: v1(136.55,34.54) 134.16,36.93 134.16,57.86 122.68,69.34 v1(122.68,89.71)
NETJP12_1: length 60.9
  TOP w0.127: R164.2 v1(138.94,38.99)
  BOTTOM w0.127: v1(138.94,38.99) 138.38,39.55 138.38,60.53 128.37,70.54 128.37,93.32 JP12.1
NETJP15_2: length 39.2
  TOP w0.127: R209.2 R208.1 38.42,15.56 38.42,17.08 37.85,17.65 JP15.2 ; v1(32.59,33.71) 32.59,34.87 32.06,35.41 U21.39
  L4_SIG w0.102: JP15.2 41.4,17.65 43.69,19.94 43.69,26.01 38.89,30.81 35.48,30.81 v1(32.59,33.71)
NETJP16_2: length 25.4
  TOP w0.127: JP16.2 46.61,17.14 46.61,27.43 44.32,29.72 44.32,31.93 42.61,33.64 42.61,34.1 41.8,34.9 v1(41.17,34.9) U21.21
  BOTTOM w0.127: R289.2 40.03,34.9 v1(41.17,34.9)
NETJP18_1: length 40.4
  TOP w0.127: U23.A9 v1(115.73,31.08)
  L4_SIG w0.102: JP18.1 88.9,14.99 88.9,18.41 89.79,19.3 98.42,19.3 110.23,31.11 114.2,31.11 114.51,31.42 115.39,31.42 v1(115.73,31.08)
NETJP19_1: length 42.4
  TOP w0.089: U23.C6 117.36,29.58 117.11,29.83 117.11,30.21 116.98,30.34 115.84,30.34 115.82,30.35
  TOP w0.127: v1(114.94,30.99) 115.57,30.35 115.82,30.35
  L4_SIG w0.102: JP19.1 93.09,14.61 108.08,14.61 109.22,15.75 109.22,27.94 110.79,29.51 113.46,29.51 v1(114.94,30.99)
NETJP19_3: length 123.8
  TOP w0.127: v1(87.12,55.75) 88.67,54.2 90.32,54.2 96.27,48.26 96.27,22.86 JP19.3
  BOTTOM w0.127: R280.2 116.08,119.38 111.25,114.55 111.25,109.65 109.93,108.33 109.93,92.18 111.23,90.88 111.23,80.62 87.12,56.52 v1(87.12,55.75)
NETJP20_1: length 306.3
  TOP w0.127: U5.13 26.52,125.96 v1(26.42,125.86) ; U1.3 v1(137.7,171.32)
  L4_SIG w0.102: v1(30.61,96.77) 30.61,94.49 29.34,93.22 29.34,65.41 33.5,61.24 33.5,36.73 35.41,34.82 38.02,34.82 41.53,31.32 44.63,31.32 v1(44.96,30.99)
  BOTTOM w0.127: v1(30.61,96.77) 30.61,96.9 33.91,100.2 33.91,110.87 34.8,111.76 34.8,116.08 31.11,119.76 31.11,124.84 30.1,125.86 v1(26.42,125.86) 17.4,125.86 14.48,128.78 14.48,144.27 17.27,147.07 21.59,147.07 31.11,156.59 32.64,156.59 36.45,160.4 36.45,166.12 41.4,171.07 135.64,171.07 135.89,170.81 137.16,170.81 137.67,171.32 v1(137.7,171.32) ; v1(44.96,30.99) 45.19,30.76 48.34,30.76 52.6,26.49 52.6,24.49 54.79,22.3 54.79,20.29 56.59,18.49 56.59,15.04 JP20.1
NETJP20_2: length 340.8
  L4_SIG w0.102: v1(29.97,96.01) 29.97,94.49 29.08,93.6 29.08,65.33 33.22,61.19 33.22,36.6 35.31,34.52 37.95,34.52 41.61,30.86 v1(43.69,30.86) ; v1(137.7,168.68) 137.7,164.11 134.8,161.21 127.64,161.21 126.67,162.18 121.64,162.18 119.99,163.83 109.09,163.83 105.79,160.53 103,160.53 100.46,157.99 v1(100.2,157.99) 98.93,157.99 97.54,159.38 96.27,159.38 93.47,162.18 84.07,162.18 83.06,163.19 56.39,163.19 55.5,162.31 39.62,162.31 v1(38.48,161.16)
  BOTTOM w0.127: JP20.2 56.21,15.06 56.21,18.26 54.25,20.22 54.25,22.12 52.2,24.18 52.2,26.32 48.17,30.35 44.2,30.35 v1(43.69,30.86) ; SB54.1 107.95,130.56 107.95,132.99 106.58,134.37 106.58,151.71 100.3,157.99 v1(100.2,157.99) ; v1(29.97,96.01) 31.5,96.01 34.29,98.81 34.29,110.67 35.05,111.43 35.05,116.33 31.5,119.89 31.5,125.22 30.38,126.34 17.55,126.34 14.99,128.91 14.99,144.4 17.02,146.43 21.59,146.43 31.27,156.11 32.67,156.11 37.08,160.53 37.85,160.53 v1(38.48,161.16)
NETJP21_1: length 43.2
  TOP w0.127: U23.G1 119.36,26.56 120.78,25.15 v1(120.78,24.89)
  L4_SIG w0.089: 119.94,28.13 119.94,26.92 120.19,26.67
  L4_SIG w0.102: v1(120.78,24.89) 120.78,26.09 120.19,26.67 ; 119.94,28.13 118.98,29.08 118.87,29.08 117.6,30.35 117.6,30.99 117.25,31.34 117.25,31.65 114.05,34.85 114.05,36.07 114.44,36.46 114.44,37.33 113.92,37.85 113.92,46.35 116.84,49.28 v1(116.84,57.91)
  BOTTOM w0.127: JP21.1 v1(116.84,57.91)
NETJP21_2: length 151.8
  TOP w0.127: v1(53.26,79.86) 53.85,79.27 53.85,77.83 67.6,64.08 67.6,60.06 68.9,58.76 95.84,58.76 97.28,60.2 109.09,60.2 111.38,57.91
  L4_SIG w0.102: v1(36.58,126.87) 35.31,128.14 35.31,143.26 38.23,146.18 38.23,147.7 v1(39.24,148.72)
  BOTTOM w0.127: SB24.1 39.24,149.22 v1(39.24,148.72) ; v1(53.26,79.86) 53.24,79.86 44.04,89.05 44.04,108.61 37.85,114.81 37.85,125.48 36.58,126.75 v1(36.58,126.87)
NETJP21_3: length 135
  TOP w0.127: SB11.2 77.98,121.41 79.5,119.89 106.68,119.89 109.98,116.59 120.02,116.59 124.08,112.52 v1(124.46,112.52) ; R75.1 135,120.02 133.86,121.16 133.6,121.16 v1(133.48,121.28) 133.22,121.54 U6.30
  BOTTOM w0.127: JP21.3 109.98,59.05 109.98,62.87 111.12,64.01 113.18,64.01 121.54,72.36 121.54,92.66 125.07,96.19 125.07,102.57 123.7,103.94 122.89,103.94 122.43,104.39 122.43,110.74 123.19,111.51 123.95,111.51 124.46,112.01 v1(124.46,112.52) 125.98,112.52 126.87,113.41 130.94,113.41 132.59,115.06 132.59,120.4 v1(133.48,121.28)
NETJP22_1: length 43.3
  TOP w0.089: U23.F2 119.11,27.83 120.07,27.83 120.37,27.53 v2(120.4,27.53)
  L4_SIG w0.102: v1(116.84,61.85) 117.35,61.34 117.35,48.77 114.48,45.9 114.48,38.05 115.19,37.34 115.19,34.39 118.34,31.24 118.52,31.24 120.4,29.36 v2(120.4,27.53)
  BOTTOM w0.127: JP22.1 116.08,62.61 v1(116.84,61.85)
NETJP22_2: length 152.7
  TOP w0.127: v1(57.15,144.91) 52.7,144.91 51.05,146.56 v1(48.77,146.56) ; v1(47.12,115.44) 47.12,89.28 55.5,80.9 55.5,77.34 68.2,64.64 68.2,60.45 69.24,59.41 94.54,59.41 96.34,61.21 109.98,61.21 111.38,62.61
  BOTTOM w0.127: v1(47.12,115.44) 47.12,120.65 50.04,123.57 50.04,125.22 54.48,129.67 54.48,138.68 57.15,141.35 v1(57.15,144.91) ; SB22.2 48.26,146.05 v1(48.77,146.56)
NETJP22_3: length 132.5
  TOP w0.127: SB10.2 77.98,124.97 76.96,123.95 76.96,120.9 78.61,119.25 100.46,119.25 100.58,119.38 106.17,119.38 109.86,115.7 119.76,115.7 v1(123.19,112.27) ; U6.31 133.48,122.04 v1(133.6,121.92)
  BOTTOM w0.127: JP22.3 110.87,64.64 112.57,64.64 120.9,72.97 120.9,93.04 124.61,96.75 124.61,102.34 123.39,103.56 122.58,103.56 121.92,104.22 121.92,111 v1(123.19,112.27) 125.22,114.3 130.05,114.3 131.83,116.08 131.83,120.9 132.84,121.92 v1(133.6,121.92)
NETJP23_3: length 3.4
  TOP w0.127: R300.1 109.98,52.7 JP23.3
NETJP24_1: length 63.7
  TOP w0.127: JP24.1 40.89,95.5 R302.1 37.97,96.14 37.97,104.14 38.73,104.9 38.73,114.81 v1(34.54,119) ; R30.2 22.23,147.45 22.86,146.81 v1(22.99,146.81)
  BOTTOM w0.127: v1(34.54,119) 33.66,119 33.02,119.63 33.02,125.73 28.07,130.68 28.07,141.1 22.99,146.18 v1(22.99,146.81)
NETJP24_3: length 2.6
  TOP w0.127: JP24.3 40.77,91.06 R299.1
NETL2_1: length 19.5
  TOP w0.508: v1(17.65,106.17) 19.56,106.17 19.94,106.55 R103.2 ; L2.1 R84.2 v1(11.43,113.06) SB12.2
  L4_SIG w0.508: v1(11.43,113.06) 11.43,111.38 16.64,106.17 v1(17.65,106.17)
NETLD1_2: length 110.5
  TOP w0.127: LD1.2 R207.2 27.3,13.97 27.94,14.61 v1(27.94,16.13) ; R299.2 v1(39.88,89.53)
  BOTTOM w0.127: v1(39.88,89.53) 40.92,89.53 52.07,78.38 52.07,68.83 57.66,63.25 57.66,45.21 53.77,41.33 51.49,41.33 49.02,38.86 49.02,36.32 45.09,32.38 44.2,32.38 42.8,30.99 42.8,27.94 43.56,27.18 43.56,19.3 41.66,17.4 36.83,17.4 35.56,16.13 v1(27.94,16.13)
NETLD2_2: length 2.5
  TOP w0.127: LD2.2 R206.2
NETLD3_2: length 128.7
  TOP w0.127: R205.2 v1(22.35,13.08) LD3.2 ; v1(99.44,19.3) 99.44,49.4 104.52,54.48 R300.2
  BOTTOM w0.127: v1(99.44,19.3) 67.59,19.3 64.64,16.35 64.64,13.43 59.97,8.76 57.5,8.76 56.87,9.4 30.23,9.4 26.54,13.08 v1(22.35,13.08)
NETLD4_2: length 2.5
  TOP w0.127: R204.2 LD4.2
NETLD5_1: length 1.5
  TOP w0.127: LD5.1 R96.1
NETLD5_2: length 2.4
  TOP w0.254: LD5.2 v1(10.16,110.74)
  BOTTOM w0.254: T6.3 v1(10.16,110.74)
NETLD6_1: length 2.2
  TOP w0.508: LD6.1 v1(16,107.82)
  BOTTOM w0.508: v1(16,107.82) R282.1
NETLD6_2: length 21.9
  TOP w0.254: R122.2 24.14,101.09 25.67,102.62 26.69,102.62 27.2,103.12 U8.10
  TOP w0.508: R122.2 R121.2 v1(22.86,102.49) ; v1(14.99,109.6) 15.75,110.36 LD6.2 17.09,111.45 U7.3
  L4_SIG w0.508: v1(14.99,109.6) 15.37,109.6 22.48,102.49 v1(22.86,102.49)
NETLD7_1: length 1.5
  TOP w0.127: R118.1 LD7.1
NETLD7_2: length 2.7
  TOP w0.254: LD7.2 13.72,101.85 v1(13.97,101.85)
  BOTTOM w0.254: T7.3 13.84,102.02 13.97,101.9 v1(13.97,101.85)
NETLD8_1: length 1.5
  TOP w0.127: R133.1 LD8.1
NETLD8_2: length 6.2
  TOP w0.508: LD8.2 8.89,92.05 ; LD8.2 8.89,90.83 ; LD8.2 9.54,91.44 ; 11.62,92.51 U11.3 12.14,93.29 ; 11.43,90.4 R134.2 10.83,89.79 ; 11.43,90.83 R132.2 ; R132.2 10.83,91.44 ; R132.2 11.43,92.05
NETLD9_1: length 1.5
  TOP w0.127: LD9.1 R135.1
NETLD9_2: length 2.9
  TOP w0.127: LD9.2 13.8,85.51 T2.3
NETLD10_1: length 1.5
  TOP w0.127: LD10.1 R142.1
NETLD11_1: length 1.7
  TOP w0.127: R200.2 LD11.1
NETLD11_2: length 56
  TOP w0.127: LD11.2 v1(13.34,16.51)
  TOP w0.508: U17.8 32.72,55.84 v1(32.64,55.75) 31.88,54.99 R156.2
  BOTTOM w0.127: v1(13.34,16.51) 13.84,17.02 21.69,17.02 25.91,21.23 25.91,24.49 29.21,27.79 29.21,32.56 30.78,34.14 30.78,53.9 v1(32.64,55.75)
NETLD12_2: length 1.9
  TOP w0.127: LD12.2 15,13.7 R201.2
NETLD12_3: length 1.9
  TOP w0.127: R202.2 16.5,13.73 LD12.3
NETLD12_4: length 5.3
  TOP w0.127: R203.1 17.78,10.45 LD12.4
NETR2_2: length 2.6
  TOP w0.508: U1.1 139.6,168.51 R2.2
NETR4_2: length 2.7
  TOP w0.127: R4.2 SW1.2
NETR20_1: length 13.8
  TOP w0.127: R21.1 R20.1 84.58,147.57 84.58,144.82 v3(84.61,144.82) ; v5(81.21,140.09) U4.E5
  L4_SIG w0.102: v5(81.21,140.09) 81.57,140.44 82.07,140.44 82.37,140.74 82.37,140.95 82.66,141.24 82.87,141.24 83.59,141.96 83.59,143.15 84.58,144.15 84.58,144.81 84.6,144.82 v3(84.61,144.82)
NETR22_1: length 14.2
  TOP w0.102: 76.81,144.02 U4.K1
  TOP w0.127: R22.1 71.88,148.84 73.66,147.07 76.07,147.07 76.81,146.33 76.81,144.02
NETR24_1: length 13.1
  TOP w0.127: R24.1 71.5,147.83 74.93,144.4 76.07,144.4 76.45,144.02 76.45,143.05 76.44,143.04 76.44,142.73 76.45,142.72 76.45,142.37 76.73,142.09 U4.K2
NETR25_1: length 3.1
  TOP w0.203: R25.1 137.47,146.56 X3.1
NETR26_1: length 12.6
  TOP w0.127: U4.L2 75.61,142.49 75.61,143.26 75.21,143.66 74.4,143.66 73.79,144.27 73.28,144.27 72.9,144.65 72.9,145.8 71.25,147.45 68.83,147.45 68.2,146.81 R26.1
NETR27_1: length 2.2
  TOP w0.127: R28.2 R27.1
NETR27_2: length 172.5
  TOP w0.127: v1(22.23,144.53) 16.64,144.53 R27.2
  L4_SIG w0.102: v1(26.49,92.43) 27,91.92 27,86.66 27.18,86.49 27.18,64.72 30.48,61.42 30.48,36.45 35.86,31.06 39.01,31.06 44.07,26.01 44.07,19.81 41.53,17.27 41.53,9.4 37.72,5.59 RV1.2
  BOTTOM w0.127: v1(26.49,92.43) 28.55,92.43 35.43,99.31 35.43,116.33 31.88,119.89 31.88,125.48 27.51,129.84 27.51,140.39 23.37,144.53 v1(22.23,144.53)
NETR31_1: length 11
  TOP w0.127: U4.B1 83.21,143.18 83.92,143.89 86.74,143.89 88.77,145.92 R31.1 89.79,146.56 89.66,146.69 SB3.2 SB4.2
NETR34_1: length 81.2
  TOP w0.127: v1(98.93,145.92) 98.17,146.69 93.16,146.69 92.65,146.17 92.65,145.99 91.95,145.29 90.42,145.29 R34.1 88.39,144.65 87.12,143.38 83.95,143.38 83.58,143.01 83.58,142.73 83.21,142.37 U4.B2 ; v1(127.03,102.67) 127.03,102.59 SB17.2 SB18.2 SB16.2
  L4_SIG w0.102: v1(127.03,102.67) 127,102.69 125.97,102.69 123.69,104.98 122.99,104.98 120.14,107.82 116.08,107.82 v1(105.61,118.29)
  BOTTOM w0.127: v1(98.93,145.92) 102.36,142.49 102.36,132.82 104.52,130.66 104.52,125.09 105.28,124.33 105.28,118.62 v1(105.61,118.29)
NETR35_1: length 10.2
  TOP w0.127: SB6.2 92.71,143.89 90.3,143.89 R35.1 88.01,143.38 87.51,142.89 U4.A1
NETR37_1: length 10.4
  TOP w0.127: SB8.2 92.65,141.67 90.36,141.67 R37.1 89.25,141.7 84.82,141.7 84.43,142.09 U4.A2
NETR39_1: length 31.5
  TOP w0.127: v1(99.19,138.18) 93.44,138.18 92.49,139.13 90.36,139.13 R39.1 89.79,140.59 SB7.2 87.41,140.84 86.93,141.32 84.04,141.32 U4.A3
  L4_SIG w0.102: v1(111.82,137.97) 108.53,137.97 108.2,138.3 105.03,138.3 104.52,137.79 99.57,137.79 v1(99.19,138.18)
  BOTTOM w0.127: R247.2 111.12,137.29 111.81,137.97 v1(111.82,137.97)
NETR41_1: length 10.2
  TOP w0.127: U4.L3 v5(75.61,141.69) ; v1(68.2,139.7) 67.56,139.06 R41.1
  L4_SIG w0.102: v5(75.61,141.69) 75.61,141.65 75.23,141.27 71.15,141.27 69.57,139.7 v1(68.2,139.7)
NETR42_1: length 9.7
  TOP w0.127: v5(74.81,140.09) U4.M5 ; v1(68.2,137.29) 68.07,137.16 R42.1
  L4_SIG w0.102: v5(74.81,140.09) 74.42,139.7 74.42,139.2 74.16,138.93 73.95,138.93 72.56,137.54 68.45,137.54 v1(68.2,137.29)
NETR43_1: length 8.1
  TOP w0.127: R43.1 88.09,136.78 86.88,137.99 86.88,138.51 86.58,138.81 85.09,138.81 84.71,139.19 84.23,139.19 84.16,139.26 83.58,139.26 U4.B6
NETR44_1: length 7.9
  TOP w0.127: R44.1 88.65,135.76 87,137.41 85.47,137.41 84.38,138.51 83.63,138.51 U4.B7
NETR45_1: length 3.1
  TOP w0.127: U6.46 126.27,126.97 125.48,127.76 125.35,127.76 124.71,128.4 R45.1
NETR46_1: length 2.7
  TOP w0.127: R46.1 125.98,128.02 126.77,127.23 U6.45
NETR46_2: length 21.1
  TOP w0.127: v1(124.61,140.39) 124.61,140.28 124.74,140.16 124.74,136.25 125.35,135.64 125.35,130.68 R46.2
  L4_SIG w0.102: v1(124.61,140.39) 120.09,140.39 117.35,137.64 v1(117.35,137.03)
  BOTTOM w0.127: SB45.2 116.94,137.44 v1(117.35,137.03)
